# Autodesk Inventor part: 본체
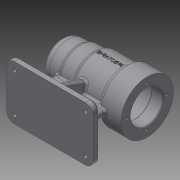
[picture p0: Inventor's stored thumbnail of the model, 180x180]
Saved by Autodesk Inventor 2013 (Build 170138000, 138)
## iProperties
Created: 2016-06
Part Number: 본체
Material: 일반
Document SubType Name: Modeling
Designer: Administrator
Density: 1 g/cm^3
Author: Administrator
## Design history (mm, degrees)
sketch "스케치1"
  geometry: L1 (-56, 34)-(28, 34); L2 (56, 34)-(56, 0); L3 (56, 0)-(-56, 0); L4 (-56, 0)-(-56, 25); L5 (28, 34)-(28, 30); L6 (28, 30)-(-11, 30); L7 (-11, 30)-(-11, 27); L8 (-11, 27)-(-31, 27); L9 (-31, 27)-(-31, 25); L10 (-31, 25)-(-56, 25); L11 (28, 34)-(56, 34); L12 (-56, 25)-(-56, 34); L13 (-56, -60)-(56, -60); L14 (56, -60)-(56, -70); L15 (56, -70)-(-56, -70); L16 (-56, -70)-(-56, -60); L17 (-36, 0)-(36, 0); L18 (36, 0)-(36, -60); L19 (36, -60)-(-36, -60); L20 (-36, -60)-(-36, 0); 3 further points
  constraints: 40 end point, 13 parallel, 5 perpendicular, 4 horizontal, 2 midpoint, 2 point on line, 1 coincident, 1 vertical alignment
  dimensions: "d0" = 112 distance of L1.start L2.start; "d2" = 68 diameter of L1 L3; "d3" = 84 distance between parallel lines of L5 L4; "d4" = 45 distance between parallel lines of L7 L4; "d5" = 25 distance between parallel lines of L9 L4; "d6" = 60 diameter of L6 L3; "d7" = 54 diameter of L8 L3; "d8" = 50 diameter of L10 L3; "d9" = 10 distance between parallel lines of L15 L13; "d11" = 70 distance from line of L15 point (0, 0); "d12" = 20 distance from line of L19.end L16; "d13" = 20 distance between parallel lines of L18 L14; "d15" = 72 distance between parallel lines of L18 L20
revolve "회전1" stored, may be unused: angle "d16" = 90 deg
extrude "돌출1" join sketch "스케치1" stored distance "d17" = 70; taper "d18" = 0 deg
extrude "돌출2" join sketch "스케치1" stored distance "d19" = 8; taper "d20" = 0 deg
sketch "스케치2"
  geometry: L1 (-60, -35)-(-70, -35) reference; L2 (-70, -35)-(-70, 35) reference; L3 (-70, 35)-(-60, 35) reference; L4 (-60, 35)-(-60, 4) reference; L5 (-60, 4)-(-29.732, 4) reference; L6 (-29.732, -4)-(-60, -4) reference; L7 (-60, -4)-(-60, -35) reference; L8 (-60, 28)-(0, 6.162); L9 (0, 6.162)-(0, -6.162); L10 (0, -6.162)-(-60, -28); L11 (-60, -28)-(-60, 28); A1 r 30 centre (0, 0) between (-29.732, -4) and (-29.732, 4) reference; 1 further point
  constraints: 8 end point, 2 parallel, 2 point on line
  dimensions: "d21" = 7 distance from line of L8.start L3; "d22" = 7 distance from line of L10.end L1; "d23" = 110 deg angle of L4 L8; "d24" = 110 deg angle of L7 L10; "d25" = 60 distance from line of L7 L9.end
extrude "돌출3" join sketch "스케치2" stored distance "d26" = 8; taper "d27" = 0 deg
sketch "스케치3"
  geometry: 2 further points
  dimensions: "d28" = 25 vertical distance of point (56, 35) point (10, 60); "d29" = 46 horizontal distance of point (56, 35) point (10, 60)
hole "구멍1" sketch "스케치3" at (10, 60) diameter "d30" = 5; stored, may be unused: countersink angle "d34" = 90 deg, drill point angle "d36" = 118 deg; dims "d31" = 6, "d32" = 9, "d33" = 4, "d35" = 8
sketch "스케치4"
  geometry: L1 (-56, -25)-(-56, 25) reference; L2 (-56, 25)-(-31, 25) reference; L3 (-31, 25)-(-31, 27) reference; L4 (-31, 27)-(-11, 27) reference; L5 (-11, 27)-(-11, 30) reference; L6 (-11, 30)-(28, 30) reference; L7 (28, 30)-(28, 34) reference; L8 (28, 34)-(56, 34) reference; L9 (56, 34)-(56, -34) reference; L10 (56, -34)-(36, -34) reference; L11 (36, -34)-(36, -60) reference; L12 (36, -60)-(56, -60) reference; L13 (56, -60)-(56, -70) reference; L14 (56, -70)-(-56, -70) reference; L15 (-56, -70)-(-56, -60) reference; L16 (-56, -60)-(-36, -60) reference; L17 (-36, -60)-(-36, -25) reference; L18 (-36, -25)-(-56, -25) reference; L19 (56, 0)-(-50, 0); L20 (56, 21)-(56, 0); L21 (56, 21)-(41, 21); L22 (41, 21)-(41, 24); L23 (41, 24)-(-13, 24); L24 (-13, 24)-(-13, 21); L25 (-13, 21)-(-25, 21); L26 (-25, 21)-(-25, 17.5); L27 (-25, 17.5)-(-43, 17.5); L28 (-43, 17.5)-(-43, 16); L29 (-43, 16)-(-47, 16); L30 (-47, 16)-(-47, 10.5); L31 (-47, 10.5)-(-50, 10.5); L32 (-50, 10.5)-(-50, 0); 1 further point
  constraints: 28 end point, 6 parallel, 6 perpendicular, 2 collinear, 1 midpoint, 1 point on line
  dimensions: "d45" = 15 distance of L20.start L21.end; "d47" = 54 distance of L22.end L23.end; "d48" = 12 distance of L24.end L25.end; "d49" = 18 distance of L26.end L27.end; "d50" = 4 distance of L28.end L29.end; "d51" = 3 distance of L30.end L31.end; "d52" = 42 diameter of L21 L19; "d53" = 48 diameter of L23 L19; "d54" = 42 diameter of L25 L19; "d55" = 35 diameter of L27 L19; "d56" = 32 diameter of L29 L19; "d57" = 21 diameter of L31 L19
revolve "회전2" sketch "스케치4" stored, may be unused: angle "d58" = 90 deg
fillet "모깎기1" dims "d59" = 10
sketch "스케치5"
  geometry: C1 r 21 at (0, 0) reference; 1 further point
  constraints: 1 vertical alignment
  dimensions: "d60" = 26 distance of C1.centre point (0, 26)
hole "구멍2" sketch "스케치5" at (0, 26) diameter "d61" = 3.242; stored, may be unused: countersink angle "d65" = 90 deg, drill point angle "d67" = 118 deg; dims "d62" = 8, "d63" = 9, "d64" = 4, "d66" = 11
node "작업 평면1"
sketch "스케치6"
  geometry: L1 (47.5, -34)-(47.5, 34) reference; L2 (-4.5, -25.68)-(-4.5, -29.732) reference; L3 (-4.5, -29.732)-(19.5, -29.732) reference; L4 (19.5, -29.732)-(19.5, -29.732) reference; L5 (19.5, -29.732)-(-4.5, -29.732) reference; L6 (-4.5, -29.732)-(-4.5, -25.68) reference; L7 (-4.5, -25.68)-(-12.5, -25.68) reference; L8 (-12.5, -25.68)-(-12.5, -29.732) reference; L9 (-12.5, -29.732)-(-19.5, -29.732) reference; L10 (-19.5, -29.732)-(-19.5, -29.732) reference; L11 (-19.5, -29.732)-(-12.5, -29.732) reference; L12 (-12.5, -29.732)-(-12.5, -25.68) reference; L13 (-12.5, -25.68)-(-4.5, -25.68) reference; 2 further points
  constraints: 1 horizontal alignment, 1 other
  dimensions: "d71" = 48 distance from line of L1 point (-0.5, 0)
feature "엠보싱1" sketch "스케치6" dims "d0" = 112, "d2" = 68, "d3" = 84, "d4" = 45, "d5" = 25, "d6" = 60, "d7" = 54, "d8" = 50, "d9" = 10, "d11" = 70, "d12" = 20, "d13" = 20, "d15" = 72, "d72" = 0.5, "d73" = 0
fillet "모깎기2" dims "d74" = 10
fillet "모깎기3" dims "d75" = 3
fillet "모깎기4" dims "d76" = 0.3
fillet "모깎기5" dims "d77" = 3
chamfer "모따기1" distance "d78" = 4; stored, may be unused: second distance "d79" = 2, angle "d80" = 45 deg
fillet "모깎기6" dims "d81" = 3
fillet "모깎기7" dims "d82" = 3
fillet "모깎기8" dims "d83" = 3
fillet "모깎기9" dims "d84" = 3
fillet "모깎기10" dims "d85" = 3
chamfer "모따기2" distance "d86" = 1; stored, may be unused: second distance "d87" = 2, angle "d88" = 45 deg
fillet "모깎기11" dims "d89" = 3
node "솔리드1"
pattern_linear "직사각형 패턴1" dims "d39" = 92
pattern_circular "원형 패턴1" dims angle "d69" = 360 deg
node "투영된 루프1"
node "절단 모서리 투영1"
node "절단 모서리 투영2"
